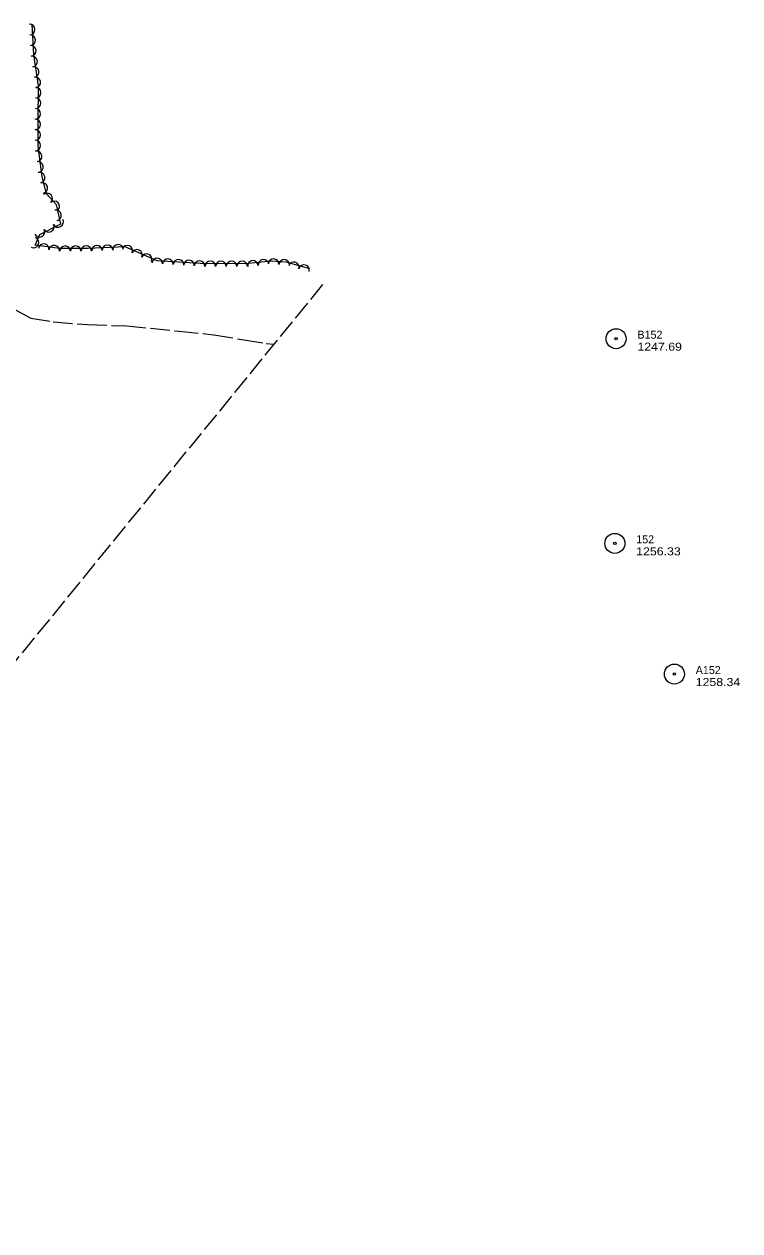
# Model space of a CAD drawing. Extents: x 298761 to 300931, y 48584 to 50968.
# Drawn here: x 300394 to 300931, y 49105 to 50010 of the extents above; entities that cross this region are included whole.
import ezdxf

# ---------------------------------------------------------------- set-up
doc = ezdxf.new("R2010")
doc.units = 0
doc.header["$LTSCALE"] = 2.4
doc.linetypes.add('LONG_DASHED', pattern=[7.5, 6, -1.5])
for name, color, linetype, lineweight in [('17', 7, 'LONG_DASHED', 13), ('18', 7, 'Continuous', 13), ('4', 7, 'Continuous', 13), ('6', 7, 'Continuous', 13)]:
    doc.layers.add(name, color=color, linetype=linetype, lineweight=lineweight)

msp = doc.modelspace()

# ---------------------------------------------------------------- linework, layer by layer
at = {"layer": '17'}
msp.add_lwpolyline([(300387.552, 49795.705), (300399.427, 49789.276), (300416.196, 49786.501), (300441.874, 49784.489), (300471.277, 49783.491), (300510.553, 49779.52), (300536.69, 49776.891), (300559.006, 49773.023), (300575.69, 49770.4), (300581.583, 49769.734)], dxfattribs=at)
at = {"layer": '18'}
msp.add_lwpolyline([(300608.596, 49826.241), (300590.675, 49831.248), (300579.82, 49832.021), (300562.229, 49830.147), (300530.434, 49830.146), (300494.084, 49832.286), (300470.141, 49842.806), (300441.836, 49841.589), (300420.971, 49841.497), (300402.739, 49843.978), (300406.291, 49851.904), (300421.791, 49860.08), (300418.685, 49874.275), (300411.233, 49882.549), (300407.972, 49895.206), (300404.823, 49918.353), (300404.797, 49936.52), (300405.229, 49963.555), (300401.711, 49986.742), (300400.339, 50009.717)], dxfattribs=at)
for centre, start, end in [((300398.501, 50005.63), 273.42514, 93.40982), ((300398.974, 49997.703), 273.42514, 93.40982), ((300399.448, 49989.776), 273.42514, 93.40982), ((300400.373, 49981.707), 278.63495, 98.61962), ((300401.564, 49973.855), 278.63495, 98.61962), ((300402.755, 49966.004), 278.63495, 98.61962), ((300403.069, 49958.44), 269.09219, 89.07687), ((300402.815, 49942.56), 269.09219, 89.07687), ((300402.942, 49950.5), 269.09219, 89.07687), ((300402.721, 49934.583), 270.08966, 90.07434), ((300402.733, 49926.642), 270.08966, 90.07434), ((300402.744, 49918.701), 270.08966, 90.07434), ((300403.787, 49910.552), 277.75482, 97.7395), ((300404.857, 49902.683), 277.75482, 97.7395), ((300405.987, 49894.579), 284.45536, 104.44004), ((300407.969, 49886.889), 284.45536, 104.44004), ((300411.646, 49878.985), 312.01553, 132.00021), ((300416.96, 49873.084), 312.01553, 132.00021), ((300418.294, 49866.337), 282.35, 102.33468), ((300405.817, 49854.004), 207.81859, 27.80326), ((300412.841, 49857.709), 207.81859, 27.80326), ((300419.864, 49861.414), 207.81859, 27.80326), ((300401.376, 49846.018), 245.86835, 65.85303), ((300409.035, 49841.024), 352.25848, 172.24316), ((300416.904, 49839.953), 352.25848, 172.24316), ((300425.099, 49839.437), 0.26029, 180.24497), ((300433.04, 49839.472), 0.26029, 180.24497), ((300440.981, 49839.507), 0.26029, 180.24497), ((300448.996, 49839.817), 2.46963, 182.45431), ((300456.93, 49840.158), 2.46963, 182.45431), ((300464.864, 49840.499), 2.46963, 182.45431), ((300471.658, 49839.869), 336.28809, 156.27276), ((300478.928, 49836.675), 336.28809, 156.27276), ((300486.198, 49833.481), 336.28809, 156.27276), ((300494.202, 49830.197), 356.63843, 176.62311), ((300502.13, 49829.73), 356.63843, 176.62311), ((300510.057, 49829.264), 356.63843, 176.62311), ((300517.985, 49828.797), 356.63843, 176.62311), ((300525.912, 49828.33), 356.63843, 176.62311), ((300533.968, 49828.068), 0.00946, 179.99414), ((300541.909, 49828.068), 0.00946, 179.99414), ((300549.85, 49828.068), 0.00946, 179.99414), ((300557.791, 49828.068), 0.00946, 179.99414), ((300565.933, 49828.451), 6.08855, 186.07323), ((300573.829, 49829.293), 6.08855, 186.07323), ((300581.363, 49829.827), 355.93442, 175.9191), ((300589.284, 49829.263), 355.93442, 175.9191), ((300596.564, 49827.445), 344.39767, 164.38235), ((300604.212, 49825.308), 344.39767, 164.38235)]:
    msp.add_arc(centre, 3.971, start, end, dxfattribs=at)
at = {"layer": '4', "linetype": 'LONG_DASHED'}
msp.add_line((300618.12, 49814.518), (299943.155, 48987.214), dxfattribs=at)
at = {"layer": '6'}
for centre, radius in [((300838.065, 49773.9), 7.5), ((300838.065, 49773.9), 0.96), ((300837.159, 49620.469), 7.5), ((300837.159, 49620.469), 0.96), ((300881.762, 49522.502), 7.5), ((300881.762, 49522.502), 0.96)]:
    msp.add_circle(centre, radius, dxfattribs=at)

# ---------------------------------------------------------------- texts
for s, p in [('B152', (300854.065, 49773.9)), ('152', (300853.159, 49620.469)), ('A152', (300897.762, 49522.502))]:
    msp.add_text(s, height=6, dxfattribs=at).set_placement(p)
at = {"layer": '6', "width": 1.15}
for s, p in [('1247.69', (300854.065, 49764.9)), ('1256.33', (300853.159, 49611.469)), ('1258.34', (300897.762, 49513.502))]:
    msp.add_text(s, height=6, dxfattribs=at).set_placement(p)

doc.saveas('drawing.dxf')
